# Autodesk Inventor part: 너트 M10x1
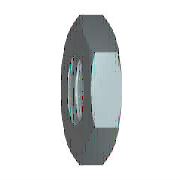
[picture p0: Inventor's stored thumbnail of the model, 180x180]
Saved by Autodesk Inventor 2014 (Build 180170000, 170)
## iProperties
Created: 2012-02
Part Number: 너트 M10x1
Material: 강철, 연강
Description: 6각 가는 너트 - 이중 모따기(부품 등급 A) - 정밀 나사산
Document SubType Name: Modeling
Standard: JIS B 1181
Designer: mduedu
Standards Organization: JIS
Language: ko-KR
Size Designation: M10x1
Categories: <MemberInstance><Categories><Category DisplayName="조임쇠" InternalName="e4da775c-781d-43d5-af7c-5136215cf5a6" Mnemonic="FSTN"><Category DisplayName="너트" InternalN
Density: 7.86 g/cm^3
Appearance: Steel
IsCustomPart: 1
Author: mduedu
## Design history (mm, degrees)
node "MSC_A1"
node "MSC_PT1"
node "MSC_PT2"
node "MSC_PF1"
body "Solid1"
sketch "스케치1"
  geometry: L1 (8, 4.619)-(8, -4.619); L2 (8, -4.619)-(0, -9.238); L3 (0, -9.238)-(-8, -4.619); L4 (-8, -4.619)-(-8, 4.619); L5 (-8, 4.619)-(0, 9.238); L6 (0, 9.238)-(8, 4.619); C1 r 8 at (0, 0); 2 further points
  constraints: 12 end point, 2 coincident, 1 centre point, 1 tangent, 1 vertical, 11 other
  dimensions: "d0" = 16 diameter of C1 (= ParS)
extrude "돌출1" new body sketch "스케치1" distance "d1" = 5 (= M); taper "d2" = 0 deg
sketch "스케치2"
  geometry: L1 (-8, 4.619)-(0, 9.238) reference; L2 (0, -9.238)-(-8, -4.619) reference; L3 (-8, 4.619)-(8, -4.619); L4 (-8, -4.619)-(8, 4.619); 1 further point
  constraints: 4 end point, 2 midpoint, 2 parallel
hole "구멍1" sketch "스케치2" diameter "d3" = 8.91747; stored, may be unused: countersink angle "d7" = 90 deg, drill point angle "d9" = 118 deg; dims "d4" = 6, "d5" = 4, "d6" = 2, "d8" = 8
chamfer "모따기1" distance "d10" = 0.5 (= 0.5 x PTC); stored, may be unused: second distance "d11" = 2, angle "d12" = 45 deg
revolve "회전1" stored, may be unused: angle "d15" = 90 deg
sketch "스케치3"
  geometry: L1 (-9.238, 5)-(-9.238, 4.285); L2 (-9.238, 4.285)-(-8, 5); L3 (-8, 5)-(-9.238, 5); L4 (-9.238, 0.715)-(-9.238, 0); L5 (-9.238, 0)-(-8, 0); L6 (-8, 0)-(-9.238, 0.715); L7 (0, 6)-(0, -1) reference; L8 (-4.619, 5)-(-9.238, 5) reference; L9 (-4.619, 0)-(-9.238, 0) reference; L10 (-9.238, 0)-(-9.238, 5) reference
  constraints: 12 end point, 4 collinear, 3 perpendicular, 2 equal length, 1 vertical
  dimensions: "d13" = 30 deg angle of L2 L3; "d14" = 8 distance from line of L2.end L7 (= 0.5 x ParS)
other parameters: "ParS" = 16 [user parameter; used in 2 equation terms], "M" = 5 [user parameter; used in 1 equation term], "PTC" = 1 [user parameter; used in 1 equation term], "d17" = 0, "d18" = 0, "d19" = 0, "d20" = 0, "d21" = 0, "d22" = 0, "d23" = 0
